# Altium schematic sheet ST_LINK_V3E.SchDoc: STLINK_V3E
size A3; Date: Not used; ApprovedBy: Not used; CheckedBy: Not used; Author: Not used; CompanyName: STMicroelectronics; DrawnBy: Not used; Engineer: Not used; Organization: Not used; Address1: Not used; Address2: Not used; Address3: Not used; Address4: Not used; DocumentNumber: 7; Revision: Not used; SheetNumber: 7; SheetTotal: 8
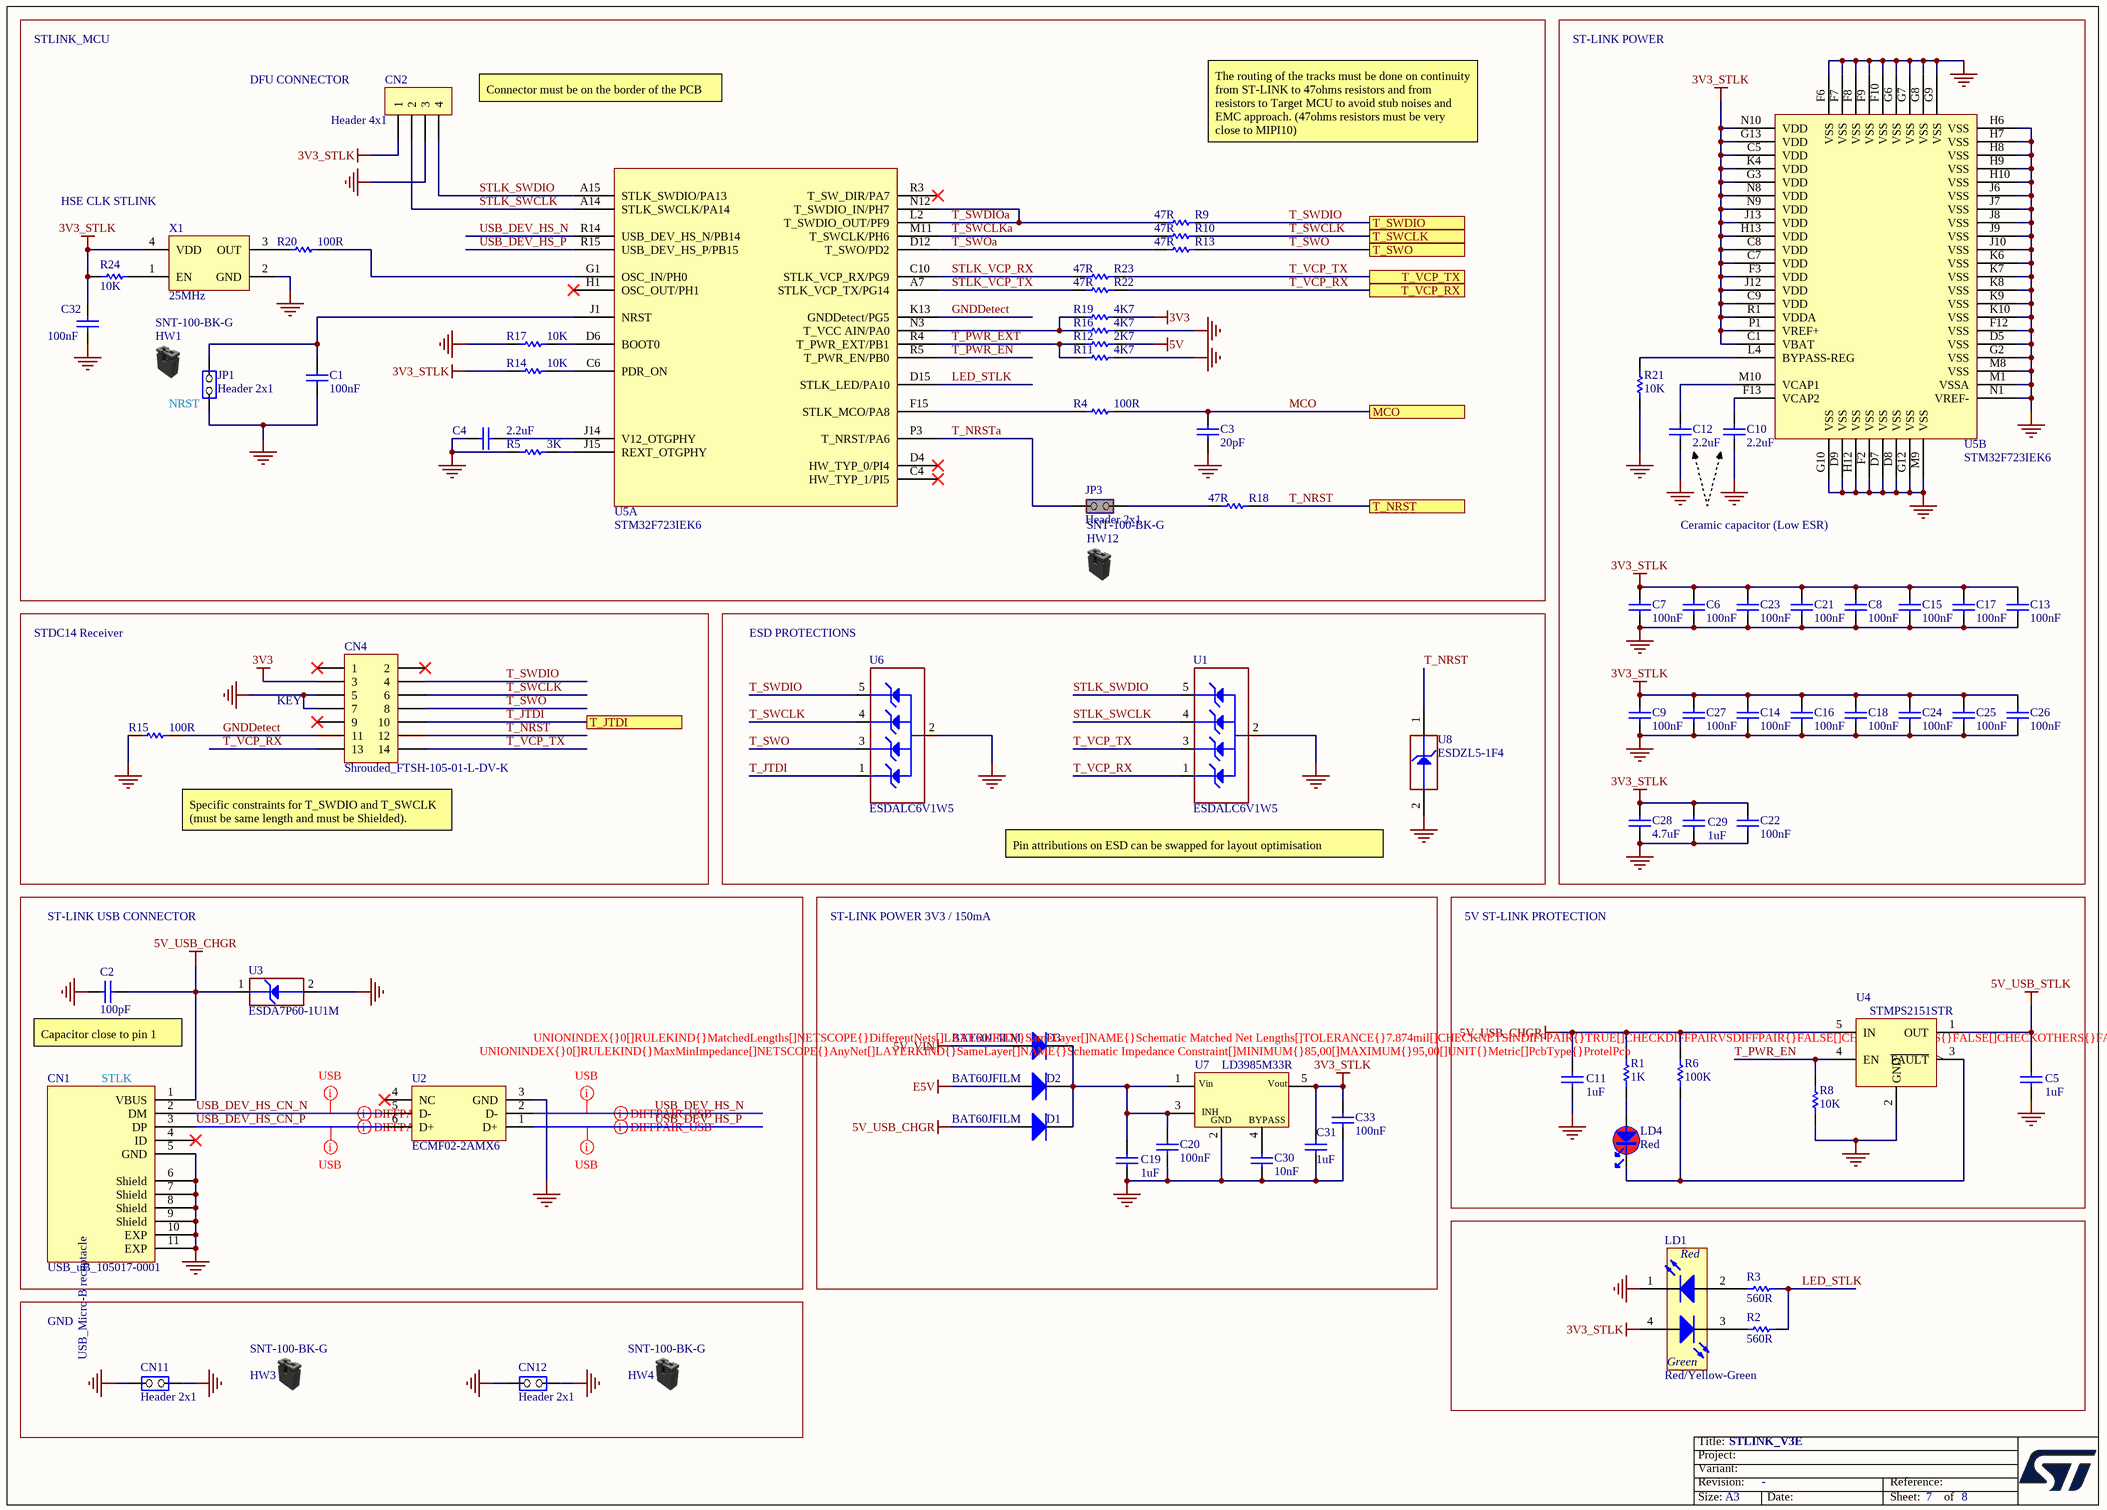
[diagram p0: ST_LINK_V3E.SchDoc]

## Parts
C1  value 100nF  [C0402]  (hidden comment: Capacitor)
C2  value 100pF  [C0402]
C3  value 20pF  [C0402]
C4  value 2.2uF  [C0603]
C5  value 1uF  [C0603]
C6  value 100nF  [C0402]  (hidden comment: Capacitor)
C7  value 100nF  [C0402]  (hidden comment: Capacitor)
C8  value 100nF  [C0402]  (hidden comment: Capacitor)
C9  value 100nF  [C0402]  (hidden comment: Capacitor)
C10  value 2.2uF  [C1206_H1P15]
C11  value 1uF  [C0603]
C12  value 2.2uF  [C1206_H1P15]
C13  value 100nF  [C0402]  (hidden comment: Capacitor)
C14  value 100nF  [C0402]  (hidden comment: Capacitor)
C15  value 100nF  [C0402]  (hidden comment: Capacitor)
C16  value 100nF  [C0402]  (hidden comment: Capacitor)
C17  value 100nF  [C0402]  (hidden comment: Capacitor)
C18  value 100nF  [C0402]  (hidden comment: Capacitor)
C19  value 1uF  [C0603]
C20  value 100nF  [C0402]  (hidden comment: Capacitor)
C21  value 100nF  [C0402]  (hidden comment: Capacitor)
C22  value 100nF  [C0402]  (hidden comment: Capacitor)
C23  value 100nF  [C0402]  (hidden comment: Capacitor)
C24  value 100nF  [C0402]  (hidden comment: Capacitor)
C25  value 100nF  [C0402]  (hidden comment: Capacitor)
C26  value 100nF  [C0402]  (hidden comment: Capacitor)
C27  value 100nF  [C0402]  (hidden comment: Capacitor)
C28  value 4.7uF  [C0603]
C29  value 1uF  [C0603]
C30  value 10nF  [C0402]
C31  value 1uF  [C0603]
C32  value 100nF  [C0402]  (hidden comment: Capacitor)
C33  value 100nF  [C0402]  (hidden comment: Capacitor)
CN1  value USB_uB_105017-0001  [CON_USBMICROB_MOLEX_105017-0001_H2P90]
CN2  value Header 4x1  [CON_SAMTEC_TSW-104-07-G-S]
CN4  value Shrouded_FTSH-105-01-L-DV-K  [CON_STDC14_Receiver_MEDIUM_WITH_MIPI10_3D]
CN11  value Header 2x1  [CON_SAMTEC_TSW-102-09-X-S]
CN12  value Header 2x1  [CON_SAMTEC_TSW-102-09-X-S]
D1  value BAT60JFILM  [DIO_SOD323]
D2  value BAT60JFILM  [DIO_SOD323]
D3  value BAT60JFILM  [DIO_SOD323]
HW1  value SNT-100-BK-G  (mechanical)
HW3  value SNT-100-BK-G  (mechanical)
HW4  value SNT-100-BK-G  (mechanical)
HW12  value SNT-100-BK-G  (mechanical)
JP1  value Header 2x1  [CON_SAMTEC_TSW-102-07-G-S]
JP3  value Header 2x1  [CON_SAMTEC_TSW-102-07-G-S]  (hidden comment: Shunt Fitted)
LD1  value Red/Yellow-Green  [LED_BI-GR_HSMF-A201-A00J1]  (hidden comment: LD_BICOLOR_CMS)
LD4  value Red  [LED_0603_VISHAY_VLMS1300-GS08_RED_1A2K_H0P8]  (hidden comment: LED_red)
R1  value 1K  [R0603]
R2  value 560R  [R0603]  (hidden comment: Resistor)
R3  value 560R  [R0603]  (hidden comment: Resistor)
R4  value 100R  [R0402]  (hidden comment: Resistor)
R5  value 3K  [R0402]
R6  value 100K  [R0603]
R8  value 10K  [R0603]
R9  value 47R  [R0402]
R10  value 47R  [R0402]
R11  value 4K7  [R0402]
R12  value 2K7  [R0402]
R13  value 47R  [R0402]
R14  value 10K  [R0402]
R15  value 100R  [R0402]  (hidden comment: Resistor)
R16  value 4K7  [R0402]
R17  value 10K  [R0402]
R18  value 47R  [R0402]
R19  value 4K7  [R0402]
R20  value 100R  [R0402]  (hidden comment: Resistor)
R21  value 10K  [R0402]
R22  value 47R  [R0402]
R23  value 47R  [R0402]
R24  value 10K  [R0402]
U1  value ESDALC6V1W5  [ESD_SOT323-5L]
U2  value ECMF02-2AMX6  [ESD_QFN-6L_1P7X1P5_P050]  (hidden comment: ​)
U3  value ESDA7P60-1U1M  [ESD_QFN2_1P6X1_P125]
U4  value STMPS2151STR  [MOS_SOT23-5L]
U5  value STM32F723IEK6  [ICC_UFBGA201_176+25_10X10_P065]  (parts A,B of 2)
U6  value ESDALC6V1W5  [ESD_SOT323-5L]
U7  value LD3985M33R  [REG_SOT23-5L]
U8  value ESDZL5-1F4  [ESD_0201_H0P3_1K_2A]  (hidden comment: ESD-TRANSIL)
X1  value 25MHz  [OSC_NDK_NZ2520SB_4P]

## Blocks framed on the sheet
ESD PROTECTIONS: U1 U6 U8
ST-LINK POWER 3V3 / 150mA: C19 C20 C30 C31 C33 D1-D3 U7
5V ST-LINK PROTECTION: C5 C11 LD4 R1 R6 R8 U4
GND: CN11 CN12 HW3 HW4

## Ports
MCO, T_JTDI, T_NRST, T_SWCLK, T_SWDIO, T_SWO, T_VCP_RX, T_VCP_TX

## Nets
3V3: CN4.3 R19.2
3V3_STLK: C6.2 C7.2 C8.2 C9.2 C13.2 C14.2 C15.2 C16.2 C17.2 C18.2 C21.2 C22.2 C23.2 C24.2 C25.2 C26.2 C27.2 C28.2 C29.2 C31.2 C32.2 C33.2 CN2.1 LD1.4(YellowGreen_anode) R14.1 R24.1 U5.C1(VBAT) U5.C5(VDD) U5.C7(VDD) U5.C8(VDD) U5.C9(VDD) U5.F3(VDD) U5.G3(VDD) U5.G13(VDD) U5.H13(VDD) U5.J12(VDD) U5.J13(VDD) U5.K4(VDD) U5.N8(VDD) U5.N9(VDD) U5.N10(VDD) U5.P1(VREF+) U5.R1(VDDA) U7.5(Vout) X1.4(VDD)
5V: R12.1
5V_USB_CHGR: C2.2 C11.2 CN1.1(VBUS) D1.1(A) R1.2 R6.2 U3.1(IO1) U4.5(IN)
5V_USB_STLK: C5.2 U4.1(OUT)
5V_VIN: D3.1(A)
E5V: D2.1(A)
GND: C1.1 C2.1 C3.1 C4.1 C5.1 C6.1 C7.1 C8.1 C9.1 C10.1 C11.1 C12.1 C13.1 C14.1 C15.1 C16.1 C17.1 C18.1 C19.1 C20.1 C21.1 C22.1 C23.1 C24.1 C25.1 C26.1 C27.1 C28.1 C29.1 C30.1 C31.1 C32.1 C33.1 CN1.5(GND) CN1.6(Shield) CN1.7(Shield) CN1.8(Shield) CN1.9(Shield) CN1.10(EXP) CN1.11(EXP) CN2.3 CN4.5 CN4.7 CN11.1(COMMON) CN11.2(NO) CN12.1(COMMON) CN12.2(NO) JP1.1(COMMON) LD1.1(RED_cathode) R5.1 R8.2 R11.1 R15.1 R16.2 R17.1 R21.1 U1.2(GND) U2.3(GND) U3.2(GND) U4.2(GND) U5.D5(VSS) U5.D7(VSS) U5.D8(VSS) U5.D9(VSS) U5.F2(VSS) U5.F6(VSS) U5.F7(VSS) U5.F8(VSS) U5.F9(VSS) U5.F10(VSS) U5.F12(VSS) U5.G2(VSS) U5.G6(VSS) U5.G7(VSS) U5.G8(VSS) U5.G9(VSS) U5.G10(VSS) U5.G12(VSS) U5.H6(VSS) U5.H7(VSS) U5.H8(VSS) U5.H9(VSS) U5.H10(VSS) U5.H12(VSS) U5.J6(VSS) U5.J7(VSS) U5.J8(VSS) U5.J9(VSS) U5.J10(VSS) U5.K6(VSS) U5.K7(VSS) U5.K8(VSS) U5.K9(VSS) U5.K10(VSS) U5.M1(VSSA) U5.M8(VSS) U5.M9(VSS) U5.N1(VREF-) U6.2(GND) U7.2(GND) U8.2(GND) X1.2(GND)
GNDDetect: CN4.11 R15.2 U5.K13(GNDDetect/PG5)
LED_STLK: R2.2 R3.2 U5.D15(STLK_LED/PA10)
MCO: C3.2 R4.2 ; port MCO
STLK_SWCLK: CN2.2 U1.4(IO3) U5.A14(STLK_SWCLK/PA14)
STLK_SWDIO: CN2.4 U1.5(IO4) U5.A15(STLK_SWDIO/PA13)
STLK_VCP_RX: R23.1 U5.C10(STLK_VCP_RX/PG9)
STLK_VCP_TX: R22.1 U5.A7(STLK_VCP_TX/PG14)
T_JTDI: CN4.10 U6.1(IO1) ; port T_JTDI
T_NRST: CN4.12 R18.2 U8.1(IO1) ; port T_NRST
T_NRSTa: JP3.1(COMMON) U5.P3(T_NRST/PA6)
T_PWR_EN: R8.1 U4.4(EN) U5.R5(T_PWR_EN/PB0)
T_PWR_EXT: R11.2 R12.2 U5.R4(T_PWR_EXT/PB1)
T_SWCLK: CN4.6 R10.2 U6.4(IO3) ; port T_SWCLK
T_SWCLKa: R10.1 U5.M11(T_SWCLK/PH6)
T_SWDIO: CN4.4 R9.2 U6.5(IO4) ; port T_SWDIO
T_SWDIOa: R9.1 U5.L2(T_SWDIO_OUT/PF9) U5.N12(T_SWDIO_IN/PH7)
T_SWO: CN4.8 R13.2 U6.3(IO2) ; port T_SWO
T_SWOa: R13.1 U5.D12(T_SWO/PD2)
T_VCP_RX: CN4.13 R22.2 U1.1(IO1) ; port T_VCP_RX
T_VCP_TX: CN4.14 R23.2 U1.3(IO2) ; port T_VCP_TX
USB_DEV_HS_CN_N: CN1.2(DM) U2.5(D-)
USB_DEV_HS_CN_P: CN1.3(DP) U2.6(D+)
USB_DEV_HS_N: U2.2(D-) U5.R14(USB_DEV_HS_N/PB14)
USB_DEV_HS_P: U2.1(D+) U5.R15(USB_DEV_HS_P/PB15)
NetC1_2: C1.2 JP1.2(NO) U5.J1(NRST)
NetC4_2: C4.2 U5.J14(V12_OTGPHY)
NetC10_2: C10.2 U5.F13(VCAP2)
NetC12_2: C12.2 U5.M10(VCAP1)
NetC19_2: C19.2 C20.2 D1.2(K) D2.2(K) D3.2(K) U7.1(Vin) U7.3(CE)
NetC30_2: C30.2 U7.4(BYPASS)
NetJP3_2: JP3.2(NO) R18.1
NetLD1_2: LD1.2(Red_anode) R3.1
NetLD1_3: LD1.3(YellowGreen_cathode) R2.1
NetLD4_1: LD4.1 R1.1
NetLD4_2: LD4.2 R6.1 U4.3(~{FAULT})
NetR4_1: R4.1 U5.F15(STLK_MCO/PA8)
NetR5_2: R5.2 U5.J15(REXT_OTGPHY)
NetR14_2: R14.2 U5.C6(PDR_ON)
NetR16_1: R16.1 R19.1 U5.N3(T_VCC_AIN/PA0)
NetR17_2: R17.2 U5.D6(BOOT0)
NetR20_1: R20.1 X1.3(OUT)
NetR20_2: R20.2 U5.G1(OSC_IN/PH0)
NetR21_2: R21.2 U5.L4(BYPASS-REG)
NetR24_2: R24.2 X1.1(EN)

Not connected (* = marked no-connect by the designer): CN1 4(ID)*; CN4 1* 2* 9*; U2 4(NC)*; U5 C4(HW_TYP_1/PI5)* D4(HW_TYP_0/PI4)* H1(OSC_OUT/PH1)* R3(T_SW_DIR/PA7)*

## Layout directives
differential pair; rule Impedance Constraint [Min = 85.00    Max = 95.00    ]: USB_DEV_HS_CN_N, USB_DEV_HS_CN_P, USB_DEV_HS_N, USB_DEV_HS_P
rule Undefined; rule Matched Net Lengths [Tolerance = 0.2mm]; rule Impedance Constraint [Min = 85.00    Max = 95.00    ]: USB_DEV_HS_CN_N, USB_DEV_HS_CN_P, USB_DEV_HS_N, USB_DEV_HS_P

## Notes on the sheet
- STLINK_MCU
- ST-LINK POWER
- DFU CONNECTOR
- (near CN2) Connector must be on the border of the PCB
- The routing of the tracks must be done on continuity from ST-LINK to 47ohms resistors and from resistors to Target MCU to avoid stub noises and EMC approach. (47ohms resistors must be very close to MIPI10)
- HSE CLK STLINK
- (near JP1) NRST
- Ceramic capacitor (Low ESR)
- STDC14 Receiver
- (near CN4) KEY
- Specific constraints for T_SWDIO and T_SWCLK (must be same length and must be Shielded).
- Pin attributions on ESD can be swapped for layout optimisation
- ST-LINK USB CONNECTOR
- (near C2) Capacitor close to pin 1
- (near CN1) STLK

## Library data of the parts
C1 C6-C9 C13-C18 C20-C27 C32 C33 = MCD-00006: Capacitor, MLCC, 100nF, 16V, X7R, +/-10%, 0402, T=0.5mm; Manufacturer_Part_Number: CC0402KRX7R7BB104; Manufacturer: YAGEO; Part_Preference: Recommended; Partial_Alternate_Internal_Part_Number: MCD-03299; Order_Code_RS: 9402047; Component_Country_Of_Origin: China; ShowFields: YES; ID: 2474
C2 = MCD-00205: Capacitor, MLCC, 100pF, 50V, NPO, 5%, 0402, T=0,5mm; Manufacturer_Part_Number: CC0402JRNPO9BN101; Manufacturer: YAGEO; Part_Preference: Recommended; Provided_By: Subcon; Component_Country_Of_Origin: China; ID: 2658; ShowFields: YES
C3 = MCD-00016: Capacitor, MLCC, 20pF, 50V, NPO, 5%, 0402, T=0,5mm; Manufacturer_Part_Number: CC0402JRNPO9BN200; Manufacturer: YAGEO; Part_Preference: Recommended; Provided_By: Subcon; Initial_Board_Reference: MB1274; Component_Country_Of_Origin: China; ID: 2479; ShowFields: YES
C4 = MCD-00012: Capacitor, MLCC, 2.2uF, 10V, X5R, 10%, 0603, T=0,8mm; Manufacturer_Part_Number: CC0603KRX5R6BB225; Manufacturer: YAGEO; Alternate_Manufacturer_Part_Number: C0603C225K8PACTU; Alternate_Manufacturer: KEMET; BMS_Part_Number: 9142010; Part_Preference: Recommended; Partial_Alternate_Internal_Part_Number: MCD-00551; Provided_By: Subcon; Initial_Board_Reference: MB1274; Component_Country_Of_Origin: China; ID: 2467; Order_Code_RS: 2370679; ShowFields: YES
C5 C11 C19 C29 C31 = MCD-00010: Capacitor, MLCC, 1uF, 16V, X5R, 10%, 0603, T=0,8mm; Manufacturer_Part_Number: CC0603KRX5R7BB105; Manufacturer: YAGEO; Part_Preference: Recommended; Provided_By: Subcon; Initial_Board_Reference: MB1274; Component_Country_Of_Origin: China; ID: 2470; Order_Code_RS: 2370680; ShowFields: YES
C10 C12 = MCD-00008: Capacitor, MLCC, 2.2uF, 16V, X7R, 10%, 1206, T=1,15mm; Manufacturer_Part_Number: CC1206KKX7R7BB225; Manufacturer: YAGEO; Alternate_Manufacturer_Part_Number: C1206C225K4RAC; Alternate_Manufacturer: KEMET; Part_Preference: Recommended; Provided_By: Subcon; Initial_Board_Reference: MB1274; Component_Country_Of_Origin: China; ID: 2472; ShowFields: YES
C28 = MCD-00009: Capacitor, MLCC, 4.7uF, 16V, X5R, 10%, 0603, T=0.8mm; Manufacturer_Part_Number: CC0603KRX5R7BB475; Manufacturer: YAGEO; Part_Preference: Recommended; Partial_Alternate_Internal_Part_Number: MCD-03565; Provided_By: subcon; Initial_Board_Reference: MB1274; Alternate_EMS: A; Component_Country_Of_Origin: China; ID: 2471; ShowFields: YES
C30 = MCD-00011: Capacitor, MLCC, 10nF, 16V, X7R, 10%, 0402, T=0.5mm; Manufacturer_Part_Number: CC0402KRX7R7BB103; Manufacturer: YAGEO; Part_Preference: Recommended; Provided_By: Subcon; Initial_Board_Reference: MB1274; Component_Country_Of_Origin: China; ID: 2469; Order_Code_RS: 3019275; ShowFields: YES
CN1 = MCD-00028: USB-MICRO-B, 0.65mm, RA, SMT, Bottom Mount,; Manufacturer_Part_Number: 1050170001; Manufacturer: MOLEX; Part_Type: Connector; Part_Preference: Recommended; Partial_Alternate_Internal_Part_Number: MCD-04277; Provided_By: Subcon; Initial_Board_Reference: MB1274; Component_Country_Of_Origin: Unknown; ID: 2489; Order_Code_RS: 2293836; ShowFields: YES
CN2 = MCD-00029: Header, 4x1, 2,54mm, VR, TH, Height 5.84mm/2.54mm; Manufacturer_Part_Number: TSW-104-07-G-S; Manufacturer: SAMTEC; Part_Type: Connector; Part_Preference: Recommended; Partial_Alternate_Internal_Part_Number: MCD-04227; Provided_By: Subcon; Initial_Board_Reference: MB1274; Component_Country_Of_Origin: United States°; ID: 2487; Order_Code_RS: 161-2460; ShowFields: YES
CN4 = MCD-01226: Header 5x2, 1.27mm, Dual row, Straight, Surface mount, vertical male connector. 3.05mm lead. Mates with FFSD connector. Footprint compatible with FTSH-107-01-L-DV,-K,-A,-P,-ES (STDC14 MEDIUM); Manufacturer_Part_Number: FTSH-105-01-L-DV-K; Manufacturer: SAMTEC; Alternate_Manufacturer_Part_Number: P127B-2x05MGF-079-0A; Alternate_Manufacturer: JIUBABA; Part_Preference: Recommended; Partial_Alternate_Internal_Part_Number: MCD-02956, MCD-03742, MCD-03788, MCD-03996, MCD-04591; Provided_By: SUBCO; Component_Country_Of_Origin: China, Costa Rica, Malaysia, USA, Vietnam; ID: 3265; Order_Code_RS: 159-2332; ShowFields: YES
CN11 CN12 = MCD-00214: Header, 2x1, 2,54mm, VR, TH, Height 5.84mm/10.16mm; Part_Type: Connector; Manufacturer_Part_Number: TSW-102-09-G-S; Manufacturer: SAMTEC; Part_Preference: Recommended; Partial_Alternate_Internal_Part_Number: MCD-02393, MCD-03591, MCD-03719, MCD-03986, MCD-03999, MCD-04227; Provided_By: Subcon; Initial_Board_Reference: MB1319; Component_Country_Of_Origin: China, Costa Rica, Malaysia, USA, Vietnam; ID: 2652; Order_Code_RS: 180-3129; ShowFields: YES
D1-D3 = MCD-00034: BAT60JFILM; Manufacturer: STMICROELECTRONICS; Part_Type: Diode; BMS_Part_Number: 9151097; Manufacturer_HQ_COO: EU; Part_Preference: Recommended; ECCN_US: EAR99; ECCN_EU: NEC; Provided_By: Subcon; Initial_Board_Reference: MB1274; Component_Country_Of_Origin: China; ID: 2483; Order_Code_RS: 714-6879; ShowFields: YES
HW1 HW3 HW4 HW12 = MCD-00043: SHUNT 2.54mm BLACK; Manufacturer: SAMTEC; Part_Type: Misc; Manufacturer_HQ_COO: Unknown; Part_Preference: Recommended; Partial_Alternate_Internal_Part_Number: MCD-01849, MCD-01864, MCD-02388, MCD-03991, MCD-04284, MCD-04580; Provided_By: Subcon; Initial_Board_Reference: MB1274; Alternate_EMS: A; Component_Country_Of_Origin: China, Costa Rica, Malaysia, USA, Vietnam; ID: 2551; Order_Code_RS: 158-7784; ShowFields: YES
JP1 = MCD-00045: Header, 2x1, 2,54mm, VR, TH, Height 5.84mm/2.54mm; Part_Type: Connector; Manufacturer_Part_Number: TSW-102-07-G-S; Manufacturer: SAMTEC; Part_Preference: Recommended; Partial_Alternate_Internal_Part_Number: MCD-02389, MCD-02957, MCD-03720, MCD-03979, MCD-04249; Provided_By: Subcon; Initial_Board_Reference: MB1274; Component_Country_Of_Origin: China, Costa Rica, Malaysia, USA, Vietnam; ID: 2545; Order_Code_RS: 2505044; ShowFields: YES
JP3 = MCD-00683: Header, 2x1, 2,54mm, VR, TH, Height 5.84mm/2.54mm - Shunt Fitted by default; Part_Type: Connector; Manufacturer_Part_Number: TSW-102-07-G-S; Manufacturer: SAMTEC; Part_Preference: Recommended; Partial_Alternate_Internal_Part_Number: MCD-02389, MCD-02957, MCD-03720, MCD-03979, MCD-04463; Provided_By: Subcon; Initial_Board_Reference: MB1331; Component_Country_Of_Origin: China, Costa Rica, Malaysia, USA, Vietnam; ID: 3057; Order_Code_RS: 155-5312; ShowFields: YES
LD1 = MCD-02402: LED Bicolor; Part_Type: Display; Part_Preference: Not recommended; Manufacturer: EVERLIGHT; Manufacturer_Part_Number: 67-22SURSYGC/S530-A2/TR8; Alternate_Internal_Part_Number: MCD-00051; Full_Alternate_Internal_Part_Number: MCD-00051, MCD-02631; ShowFields: YES; ID: 4508
LD4 = MCD-02787: LED, Red, 1V7 to 2V2, 5mA, 0603; Part_Type: Display; Part_Preference: Recommended; Manufacturer: EVERLIGHT; Manufacturer_Part_Number: 19-217/R6C-AL1M2VY/6T; Full_Alternate_Internal_Part_Number: MCD-02401; Partial_Alternate_Internal_Part_Number: MCD-00586; ShowFields: YES; ID: 4899; Component_Country_Of_Origin: China
R1 = MCD-00070: Resistor,1K,0603,1%,1/10W; Manufacturer_Part_Number: RC0603FR-071KL; Manufacturer: YAGEO; Part_Preference: Recommended; Provided_By: Subcon; Initial_Board_Reference: MB1274; Component_Country_Of_Origin: China; ID: 2522; Order_Code_RS: 9238484RL; ShowFields: YES
R2 R3 = MCD-00490: Resistor, 560R, 0603, +/-1%, 1/10W; Manufacturer_Part_Number: RC0603FR-07560RL; Manufacturer: YAGEO; BMS_Part_Number: 9129742; Part_Preference: Recommended; Component_Country_Of_Origin: China; ID: 2787; ShowFields: YES
R4 R15 R20 = MCD-00067: Resistor, 100R, 0402, +/- 1%, 1/16W; Manufacturer_Part_Number: RC0402FR-07100RL; Manufacturer: YAGEO; Part_Preference: Recommended; Order_Code_RS: 9239111; Component_Country_Of_Origin: China; ShowFields: YES; ID: 2527
R5 = MCD-00185: Resistor,3K,0402,1%,1/16W; Manufacturer_Part_Number: RC0402FR-073KL; Manufacturer: YAGEO; Part_Preference: Recommended; Provided_By: Subcon; Component_Country_Of_Origin: China; ID: 2682; ShowFields: YES
R6 = MCD-00223: Resistor,100K,0603,1%,1/10W; Manufacturer_Part_Number: RC0603FR-07100KL; Manufacturer: YAGEO; Part_Preference: Recommended; Provided_By: Subcon; Initial_Board_Reference: MB1319; Component_Country_Of_Origin: China; ID: 2647; ShowFields: YES
R8 = MCD-00220: Resistor,10K,0603,1%,1/10W; Manufacturer_Part_Number: RC0603FR-0710KL; Manufacturer: YAGEO; Part_Preference: Recommended; Provided_By: Subcon; Initial_Board_Reference: MB1319; Component_Country_Of_Origin: China; ID: 2649; ShowFields: YES
R9 R10 R13 R18 R22 R23 = MCD-00481: Resistor,47R,0402,1%,1/16W; Manufacturer_Part_Number: RC0402FR-0747RL; Manufacturer: YAGEO; Part_Preference: Recommended; Provided_By: SUBCO; ECCN_US: EAR99; ECCN_EU: NEC; Component_Country_Of_Origin: China; ID: 2796; ShowFields: YES
R11 R16 R19 = MCD-00065: Resistor,4K7,0402,1%,1/16W; Manufacturer_Part_Number: RC0402FR-074K7L; Manufacturer: YAGEO; Alternate_Manufacturer_Part_Number: RT0402FRE074K7L; Part_Preference: Recommended; Partial_Alternate_Internal_Part_Number: MCD-03300; Provided_By: Subcon; Initial_Board_Reference: MB1274; Component_Country_Of_Origin: China; ID: 2526; Order_Code_RS: 9239316; ShowFields: YES
R12 = MCD-00055: Resistor,2K7,0402,1%,1/16W; Manufacturer_Part_Number: RC0402FR-072K7L; Manufacturer: YAGEO; Part_Preference: Recommended; Provided_By: Subcon; Initial_Board_Reference: MB1274; Component_Country_Of_Origin: China; ID: 2535; Order_Code_RS: 9239286; ShowFields: YES
R14 R17 R21 R24 = MCD-00053: Resistor,10K,0402,1%,1/16W; Manufacturer_Part_Number: RC0402FR-0710KL; Manufacturer: YAGEO; BMS_Part_Number: 9131590; Part_Preference: Recommended; Provided_By: subcon; Initial_Board_Reference: MB1274; Component_Country_Of_Origin: China; ID: 2539; Order_Code_RS: 9239359; ShowFields: YES
U1 U6 = MCD-00136: Dual Transil array for ESD protection; Part_Type: Diode; Manufacturer: STMICROELECTRONICS; BMS_Part_Number: 9151112; Manufacturer_HQ_COO: EU; Part_Preference: Recommended; ECCN_US: EAR99; ECCN_EU: NEC; Provided_By: Subcon; Initial_Board_Reference: MB1262; Component_Country_Of_Origin: China; ID: 2731; Order_Code_RS: 178-7373; ShowFields: YES
U2 = MCD-00649: Common mode filter with ESD protection for USB 2.0 interface; Part_Type: Diode; Manufacturer: STMICROELECTRONICS; BMS_Part_Number: 9151138; Manufacturer_HQ_COO: EU; Part_Preference: Recommended; ECCN_US: EAR99; ECCN_EU: NEC; Provided_By: Subcon; Initial_Board_Reference: MB1248; Component_Country_Of_Origin: China; ID: 3094; Order_Code_RS: 880-5276; ShowFields: YES
U3 = MCD-00251: High power transient voltage suppressor, 7V breakdown; Part_Type: Diode; Manufacturer: STMICROELECTRONICS; BMS_Part_Number: 9179042; Manufacturer_HQ_COO: EU; Part_Preference: Recommended; ECCN_US: EAR99; ECCN_EU: NEC; Provided_By: Subcon; Initial_Board_Reference: MB1311; Component_Country_Of_Origin: China; ID: 2618; Order_Code_RS: 110-6381; ShowFields: YES
U4 = MCD-00159: 500mA, Enhanced single channel power switches with active high enable pin; Part_Type: IC; Manufacturer: STMICROELECTRONICS; Alternate_Manufacturer_Part_Number: TPS2051C; Alternate_Manufacturer: TEXAS INSTRUMENTS; BMS_Part_Number: 9159009; Part_Preference: Recommended; ECCN_US: EAR99; ECCN_EU: NEC; Provided_By: Subcon; Initial_Board_Reference: MB1264; Component_Country_Of_Origin: Malaysia; ID: 2708; Order_Code_RS: 165-5516; ShowFields: YES
U5 = MCD-00596: STM32F723IEK  (STM32F7) BGA176; Part_Type: IC; Manufacturer: STMICROELECTRONICS; BMS_Part_Number: 9175300; Manufacturer_HQ_COO: EU; Part_Preference: Not recommended; Provided_By: SUBCO with ST control; ECCN_US: 3A991A2; ECCN_EU: NEC; Component_Country_Of_Origin: Philippines; ID: 3144; Order_Code_RS: 135-8241; ShowFields: YES
U7 = MCD-00086: Ultra low drop-low noise BiCMOS voltage, regulators low ESR capacitors compatible; Manufacturer: STMICROELECTRONICS; Part_Type: IC; BMS_Part_Number: 9176161; Manufacturer_HQ_COO: EU; Part_Preference: Recommended; ECCN_US: EAR99; ECCN_EU: NEC; Provided_By: Subcon; Initial_Board_Reference: MB1274; Component_Country_Of_Origin: China; ID: 2506; Order_Code_RS: 168-6500; ShowFields: YES
U8 = MCD-03501: Diode, ESD TVS, 5V5, 100nA, 10V, 0201; Manufacturer: STMICROELECTRONICS; Part_Preference: Recommended; Component_Country_Of_Origin: Singapore; ID: 5617; ShowFields: YES
X1 = MCD-00597: Oscillator 25.00Mhz, -+50PPM, 3.3V, Temp -55 to +125°C; Manufacturer_Part_Number: NZ2520SH-25MHz-END4869C; Manufacturer: NDK; Alternate_Manufacturer_Part_Number: KC2520B25.0000C10E00; Alternate_Manufacturer: AVX CORP/KYOCERA CORP; Part_Type: Crystal_Osc; BMS_Part_Number: 9157050; Part_Preference: Recommended; Provided_By: STM; Initial_Board_Reference: MB1331; Component_Country_Of_Origin: Japan; ID: 3148; ShowFields: YES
